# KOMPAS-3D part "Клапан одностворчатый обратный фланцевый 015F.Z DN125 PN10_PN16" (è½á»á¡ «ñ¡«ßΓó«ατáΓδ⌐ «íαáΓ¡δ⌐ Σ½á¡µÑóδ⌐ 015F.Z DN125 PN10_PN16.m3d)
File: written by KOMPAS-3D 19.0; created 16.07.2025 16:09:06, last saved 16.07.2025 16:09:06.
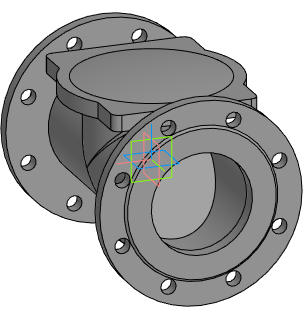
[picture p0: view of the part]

Document properties: Полное имя файла: E:\Dendor Работа Сачек\3D для проектировщиков\5.4 Тип 015F.Z. Клапан одностворчатый обратный фланцевый\stp_Клапан одностворчатый обратный фланцевый 015F.Z PN10_16\Клапан одностворчатый обратный фланцевый 015F.Z DN125 PN10_PN16.m3d

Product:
- Part/product: Клапан одностворчатый обратный фланцевый 015F.Z DN125 PN10_PN16

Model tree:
1. Операция без истории:1
2. Операция без истории:2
